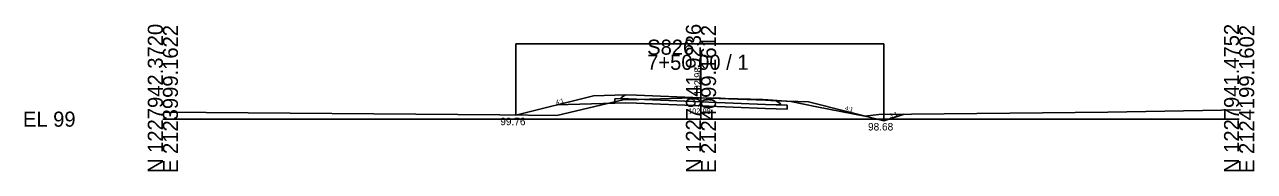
# Model space of a CAD drawing. Extents: x 2118382 to 2118616, y 1213030 to 1222057.
# Drawn here: x 2118381.9 to 2118610.4, y 1218030.1 to 1218057.3 of the extents above; entities that cross this region are included whole.
import ezdxf

# ---------------------------------------------------------------- set-up
doc = ezdxf.new("R2010")
doc.units = 0
for name, color, linetype in [('XS_CELL', 7, 'Continuous'), ('XS_M_DITCH', 7, 'Continuous'), ('XS_P_FINISHED_GRADE', 7, 'Continuous'), ('XS_P_FINISHED_GRADE_ELEV_TX', 7, 'Continuous'), ('XS_P_SUBGRADE_GRANULAR', 7, 'Continuous'), ('XS_P_SUBGRADE_PAVEMENT', 7, 'Continuous'), ('XS_P_TX_DCH', 7, 'Continuous'), ('XS_P_TX_FS_BS', 7, 'Continuous'), ('XS_X_GROUND', 7, 'Continuous'), ('XS_X_GROUND_TX', 7, 'Continuous')]:
    doc.layers.add(name, color=color, linetype=linetype)

msp = doc.modelspace()

# ---------------------------------------------------------------- linework, layer by layer
at = {"layer": 'XS_CELL'}
for p, q in [((2118507.6, 1218039.8), (2118507.6, 1218051.76)), ((2118407.6, 1218039.8), (2118507.6, 1218039.8)), ((2118507.6, 1218039.8), (2118607.6, 1218039.8))]:
    msp.add_line(p, q, dxfattribs=at)
at = {"layer": 'XS_M_DITCH'}
for p, q in [((2118473.2, 1218040.56), (2118473.2, 1218053.78)), ((2118473.2, 1218053.78), (2118541.6, 1218053.78)), ((2118541.6, 1218053.78), (2118541.6, 1218039.49))]:
    msp.add_line(p, q, dxfattribs=at)
at = {"layer": 'XS_P_FINISHED_GRADE'}
for p, q in [((2118487.6, 1218044.16), (2118473.2, 1218040.56)), ((2118493.6, 1218044.34), (2118487.6, 1218044.16)), ((2118495.6, 1218044.26), (2118493.6, 1218044.34)), ((2118495.6, 1218044.26), (2118507.6, 1218043.78)), ((2118507.6, 1218043.78), (2118519.6, 1218043.3)), ((2118519.6, 1218043.3), (2118521.6, 1218043.23)), ((2118521.6, 1218043.23), (2118527.6, 1218042.99)), ((2118527.6, 1218042.99), (2118541.6, 1218039.49)), ((2118541.6, 1218039.49), (2118545.36, 1218040.74))]:
    msp.add_line(p, q, dxfattribs=at)
at = {"layer": 'XS_P_SUBGRADE_GRANULAR'}
for p, q in [((2118491.6, 1218042.78), (2118480.78, 1218042.45)), ((2118492.71, 1218043.62), (2118491.6, 1218043.59)), ((2118491.6, 1218042.78), (2118491.6, 1218043.59)), ((2118493.6, 1218042.84), (2118491.6, 1218042.78)), ((2118495.6, 1218042.76), (2118493.6, 1218042.84)), ((2118495.6, 1218042.76), (2118507.6, 1218042.28)), ((2118507.6, 1218042.28), (2118519.6, 1218041.8)), ((2118522.45, 1218042.44), (2118523.6, 1218042.4)), ((2118523.6, 1218041.65), (2118523.6, 1218042.4)), ((2118519.6, 1218041.8), (2118521.6, 1218041.73)), ((2118521.6, 1218041.73), (2118523.6, 1218041.65))]:
    msp.add_line(p, q, dxfattribs=at)
at = {"layer": 'XS_P_SUBGRADE_PAVEMENT'}
for p, q in [((2118492.88, 1218043.91), (2118492.71, 1218043.62)), ((2118495.6, 1218043.51), (2118492.71, 1218043.62)), ((2118493.6, 1218044.34), (2118492.88, 1218043.91)), ((2118495.6, 1218043.51), (2118507.6, 1218043.03)), ((2118507.6, 1218043.03), (2118519.6, 1218042.55)), ((2118519.6, 1218042.55), (2118521.6, 1218042.48)), ((2118521.6, 1218043.23), (2118522.28, 1218042.74)), ((2118521.6, 1218042.48), (2118522.45, 1218042.44)), ((2118522.28, 1218042.74), (2118522.45, 1218042.44))]:
    msp.add_line(p, q, dxfattribs=at)
at = {"layer": 'XS_X_GROUND'}
for p, q in [((2118487.88, 1218042.15), (2118493.41, 1218043.43)), ((2118493.41, 1218043.43), (2118493.8, 1218043.44)), ((2118493.8, 1218043.44), (2118496.05, 1218043.46)), ((2118496.05, 1218043.46), (2118506.07, 1218043.74)), ((2118506.07, 1218043.74), (2118507.6, 1218043.78)), ((2118507.6, 1218043.78), (2118511.24, 1218043.68)), ((2118511.24, 1218043.68), (2118512.16, 1218043.65)), ((2118512.16, 1218043.65), (2118519.08, 1218043.44)), ((2118519.08, 1218043.44), (2118520.05, 1218043.39)), ((2118520.05, 1218043.39), (2118524.3, 1218043.09)), ((2118524.3, 1218043.09), (2118529.16, 1218042.09)), ((2118407.84, 1218041.1), (2118470.25, 1218040.58)), ((2118470.25, 1218040.58), (2118480.83, 1218040.5)), ((2118480.83, 1218040.5), (2118487.88, 1218042.15)), ((2118529.16, 1218042.09), (2118538.07, 1218040.33)), ((2118538.07, 1218040.33), (2118540.63, 1218040.69)), ((2118540.63, 1218040.69), (2118583.19, 1218041.11)), ((2118583.19, 1218041.11), (2118607.84, 1218041.54))]:
    msp.add_line(p, q, dxfattribs=at)

# ---------------------------------------------------------------- texts
at = {"layer": 'XS_CELL'}
for s, p in [('N 1227942.3720', (2118407.6, 1218029.8)), ('E 2123999.1622', (2118410.4, 1218029.8)), ('N 1227941.9236', (2118507.6, 1218029.8)), ('E 2124099.1612', (2118510.4, 1218029.8)), ('N 1227941.4752', (2118607.6, 1218029.8)), ('E 2124199.1602', (2118610.4, 1218029.8))]:
    msp.add_text(s, height=2.8, rotation=90, dxfattribs=at).set_placement(p)
for s, p in [('S826', (2118497.6, 1218051.76)), ('7+50.00 / 1', (2118497.6, 1218048.96)), ('EL 99', (2118381.6, 1218038.4))]:
    msp.add_text(s, height=2.8, dxfattribs=at).set_placement(p)
at = {"layer": 'XS_P_FINISHED_GRADE_ELEV_TX'}
msp.add_text(' 102.98', height=1.25, rotation=90, dxfattribs=at).set_placement((2118507.6, 1218043.78))
at = {"layer": 'XS_P_TX_DCH'}
for s, p in [('99.76', (2118470.31, 1218038.68)), ('98.68', (2118538.64, 1218037.7))]:
    msp.add_text(s, height=1.4, dxfattribs=at).set_placement(p)
at = {"layer": 'XS_P_TX_FS_BS'}
for s, rotation, p in [('4:1', 14.0362, (2118480.69, 1218042.52)), ('4:1', 345.9638, (2118534.3, 1218041.53)), ('3:1', 18.4349, (2118542.76, 1218040))]:
    msp.add_text(s, height=0.8, rotation=rotation, dxfattribs=at).set_placement(p)
at = {"layer": 'XS_X_GROUND_TX'}
msp.add_text('102.98', height=1, dxfattribs=at).set_placement((2118505.2, 1218040.79))

doc.saveas('drawing.dxf')
